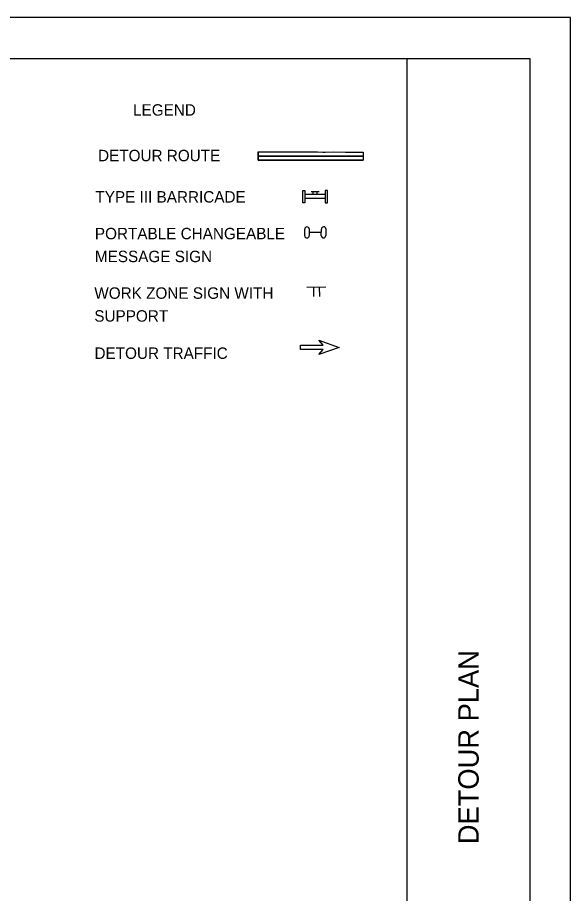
# Model space of a CAD drawing. Extents: x 0 to 680, y 0 to 440.
# Drawn here: x 544.5 to 680, y 225.4 to 440 of the extents above; entities that cross this region are included whole.
import ezdxf

# ---------------------------------------------------------------- set-up
doc = ezdxf.new("R2010")
doc.units = 0
for name, color, linetype in [('GM_X_Corporation_Text', 7, 'Continuous'), ('GM_X_County', 7, 'Continuous'), ('GM_X_Major_Lake', 7, 'Continuous'), ('GM_X_Minor_Lake', 7, 'Continuous'), ('GM_X_Minor_Lake_Text', 7, 'Continuous'), ('GM_X_Minor_River_Text', 7, 'Continuous'), ('GM_X_Township_Text', 7, 'Continuous'), ('GM_X_Unincorporated_Text', 7, 'Continuous')]:
    doc.layers.add(name, color=color, linetype=linetype)

msp = doc.modelspace()

# ---------------------------------------------------------------- linework, layer by layer
at = {"layer": 'GM_X_Corporation_Text'}
for points in [[(605.02, 406.06), (606.8, 406.06), (607.57, 406.06), (608.25, 406.06), (609.15, 406.06), (609.86, 406.06), (611.5, 406.06), (612.24, 406.06), (612.98, 406.06), (613.65, 406.06), (614.41, 406.06), (615.24, 406.06), (616.03, 406.06), (616.44, 406.07), (616.74, 406.06), (618.04, 406.06), (619.29, 406.05), (619.92, 406.05), (620.73, 406.06), (621.96, 406.06), (622.78, 406.05), (622.94, 406.05), (624.84, 406.05), (626.38, 406.04), (627.97, 406.04), (629.2, 406.04), (629.2, 405.04), (627.97, 405.04), (626.38, 405.04), (621.42, 405.06), (620.73, 405.06), (619.92, 405.05), (619.28, 405.05), (618.04, 405.06), (616.73, 405.06), (616.43, 405.07), (616.03, 405.06), (615.24, 405.06), (614.41, 405.06), (613.65, 405.06), (612.98, 405.06), (612.24, 405.06), (611.5, 405.06), (609.86, 405.06), (609.16, 405.06), (608.25, 405.06), (607.57, 405.06), (606.8, 405.06), (605.01, 405.06), (603.42, 405.07), (603.43, 406.07)], [(603.44, 407.07), (605.02, 407.06), (606.79, 407.06), (607.56, 407.06), (608.25, 407.06), (609.15, 407.06), (609.86, 407.06), (611.5, 407.06), (612.24, 407.06), (612.97, 407.06), (613.65, 407.06), (614.41, 407.06), (615.24, 407.06), (616.02, 407.06), (616.45, 407.07), (616.75, 407.06), (618.04, 407.06), (619.29, 407.05), (619.91, 407.05), (621.98, 407.06), (624.84, 407.05), (626.38, 407.04), (627.97, 407.04), (629.2, 407.04), (629.2, 406.04), (627.97, 406.04), (626.38, 406.04), (624.84, 406.05), (622.94, 406.05), (622.78, 406.05), (621.96, 406.06), (620.73, 406.06), (619.92, 406.05), (619.29, 406.05), (618.04, 406.06), (616.74, 406.06), (616.44, 406.07), (616.03, 406.06), (615.24, 406.06), (614.41, 406.06), (613.65, 406.06), (612.98, 406.06), (612.24, 406.06), (611.5, 406.06), (609.86, 406.06), (609.15, 406.06), (608.25, 406.06), (607.57, 406.06), (606.8, 406.06), (605.02, 406.06), (603.43, 406.07)]]:
    msp.add_lwpolyline(points, close=True, dxfattribs=at)
at = {"layer": 'GM_X_County'}
msp.add_lwpolyline([(0, 0), (680, 0), (680, 440), (0, 440)], close=True, dxfattribs=at)
at = {"layer": 'GM_X_Major_Lake'}
for p, q in [((616.42, 397.38), (618.42, 397.38)), ((616.92, 396.63), (616.92, 397.38)), ((617.92, 396.63), (617.92, 397.38)), ((619.92, 396.63), (614.92, 396.63)), ((619.92, 395.63), (614.92, 395.63)), ((617.42, 396.13), (617.42, 396.13)), ((619.35, 359.71), (618.35, 360.95)), ((618.35, 360.95), (623.35, 359.21)), ((613.85, 358.71), (613.85, 359.71)), ((613.85, 359.71), (619.35, 359.71)), ((613.85, 359.21), (613.85, 359.21)), ((619.35, 358.71), (613.85, 358.71)), ((623.35, 359.21), (618.35, 357.48)), ((618.35, 357.48), (619.35, 358.71)), ((623.35, 359.21), (623.35, 359.21))]:
    msp.add_line(p, q, dxfattribs=at)
for points in [[(614.42, 394.63), (614.42, 397.63), (614.92, 397.63), (614.92, 394.63)], [(620.42, 394.63), (620.42, 397.63), (619.92, 397.63), (619.92, 394.63)]]:
    msp.add_lwpolyline(points, close=True, dxfattribs=at)
at = {"layer": 'GM_X_Minor_Lake'}
for p, q in [((603.44, 407.07), (603.42, 405.07)), ((629.2, 407.04), (629.2, 405.04))]:
    msp.add_line(p, q, dxfattribs=at)
for points in [[(603.44, 407.07), (605.02, 407.06), (606.79, 407.06), (607.56, 407.06), (608.25, 407.06), (609.15, 407.06), (609.86, 407.06), (611.5, 407.06), (612.24, 407.06), (612.97, 407.06), (613.65, 407.06), (614.41, 407.06), (615.24, 407.06), (616.02, 407.06), (616.45, 407.07), (616.75, 407.06), (618.04, 407.06), (619.29, 407.05), (619.91, 407.05), (621.98, 407.06)], [(621.98, 407.06), (624.84, 407.05), (626.38, 407.04), (627.97, 407.04), (629.2, 407.04)], [(603.42, 405.07), (605.01, 405.06), (606.8, 405.06), (607.57, 405.06), (608.25, 405.06), (609.16, 405.06), (609.86, 405.06), (611.5, 405.06), (612.24, 405.06), (612.98, 405.06), (613.65, 405.06), (614.41, 405.06), (615.24, 405.06), (616.03, 405.06), (616.43, 405.07), (616.73, 405.06), (618.04, 405.06), (619.28, 405.05), (619.92, 405.05), (620.73, 405.06), (621.42, 405.06)], [(621.42, 405.06), (626.38, 405.04), (627.97, 405.04), (629.2, 405.04)]]:
    msp.add_lwpolyline(points, dxfattribs=at)
at = {"layer": 'GM_X_Minor_River_Text'}
msp.add_line((640, 10), (640, 430), dxfattribs=at)
msp.add_lwpolyline([(30, 430), (670, 430), (670, 10), (30, 10)], close=True, dxfattribs=at)
at = {"layer": 'GM_X_Township_Text'}
msp.add_line((622.78, 406.05), (622.94, 406.05), dxfattribs=at)
for points in [[(603.43, 406.07), (605.02, 406.06), (606.8, 406.06), (607.57, 406.06), (608.25, 406.06), (609.15, 406.06), (609.86, 406.06), (611.5, 406.06), (612.24, 406.06), (612.98, 406.06), (613.65, 406.06), (614.41, 406.06), (615.24, 406.06), (616.03, 406.06), (616.44, 406.07), (616.74, 406.06), (618.04, 406.06), (619.29, 406.05), (619.92, 406.05), (620.73, 406.06), (621.96, 406.06), (622.78, 406.05)], [(622.94, 406.05), (624.84, 406.05), (626.38, 406.04), (627.97, 406.04), (629.2, 406.04)]]:
    msp.add_lwpolyline(points, dxfattribs=at)
at = {"layer": 'GM_X_Unincorporated_Text'}
for p, q in [((615.99, 388.2), (615.96, 386.57)), ((618.95, 387.35), (615.97, 387.38)), ((620.06, 388.21), (620.03, 386.57)), ((615.35, 373.98), (620.07, 374.05)), ((617, 374), (617.04, 371.64)), ((617.71, 374.02), (617.71, 374.02)), ((618.42, 374.03), (618.46, 371.67))]:
    msp.add_line(p, q, dxfattribs=at)
for points in [[(614.86, 386.52), (614.89, 388.16)], [(618.93, 386.53), (618.96, 388.16)]]:
    msp.add_lwpolyline(points, dxfattribs=at)
for centre, start, end in [((615.44, 388.17), 3.0516, 181.4053), ((619.51, 388.18), 3.0516, 181.4053), ((615.41, 386.55), 183.0516, 1.4053), ((619.48, 386.56), 183.0516, 1.4053)]:
    msp.add_arc(centre, 0.55, start, end, dxfattribs=at)

# ---------------------------------------------------------------- texts
at = {"layer": 'GM_X_Minor_Lake'}
for s, p in [('LEGEND', (572.8, 415.96)), ('DETOUR ROUTE', (564.22, 404.79)), ('TYPE III BARRICADE', (563.58, 394.67)), ('PORTABLE CHANGEABLE', (563.45, 385.68)), ('MESSAGE SIGN', (563.45, 380.08)), ('WORK ZONE SIGN WITH ', (563.31, 371.1)), ('SUPPORT', (563.31, 365.5)), ('DETOUR TRAFFIC', (563.35, 356.38))]:
    msp.add_text(s, height=2.8, dxfattribs=at).set_placement(p)
at = {"layer": 'GM_X_Minor_Lake_Text'}
msp.add_text('DETOUR PLAN', height=5, rotation=90, dxfattribs=at).set_placement((657.5, 237.5))

doc.saveas('drawing.dxf')
